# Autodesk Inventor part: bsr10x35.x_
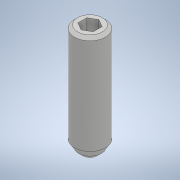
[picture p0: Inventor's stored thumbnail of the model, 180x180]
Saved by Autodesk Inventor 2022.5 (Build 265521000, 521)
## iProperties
Created: 2020-01
Part Number: bsr10x35.x_
Material: 一般
Document SubType Name: Modeling
Designer: ImaoCorp
Density: 1 g/cm^3
Appearance: 既定
Sending System: SOLIDWORKS 2018-2018316
MC: AMD64
MC_MODEL: Intel64 Family 6 Model 60 Stepping 3, GenuineIntel
OS: Windows_NT
FRU: Parasolid Version 30.0, build 310,  6- 8-2018
FORMAT: text
GUISE: transmit
KEY: bsr10x35
FILE: bsr10x35.x_t
DATE: Thu Jan 23 16:48:03 2020
Author: ImaoCorp
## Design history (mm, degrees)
feature "Base1"
node "ソリッド1"
